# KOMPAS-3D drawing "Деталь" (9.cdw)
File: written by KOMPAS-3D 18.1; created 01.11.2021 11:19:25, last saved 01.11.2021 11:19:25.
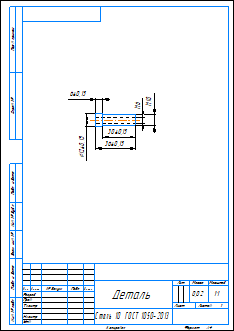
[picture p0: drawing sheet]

Sheet 1: A4, portrait

Document properties: Автор: 111; Полное имя файла: C:\Users\admin\Desktop\9.cdw; Масса: 0.0158448

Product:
- Part/product: Деталь
    Масса: 0.0158448
    source file: ffb\9.cdw

Title block, sheet 1: Наименование: Деталь; Материал: Сталь 10  ГОСТ 1050-2013; Масса: 0,02; Количество листов документа: 1; Форматы листов документа: A4

Views: Вид 1, Спереди
Referenced files in C:\Users\admin\Desktop\ffb\: 9.m3d
Dimensions and other numbers on the sheet: 36±0,15; 30±0,15; 6±0,15; 12±0,15; 10; 1:1; 1; 0,02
